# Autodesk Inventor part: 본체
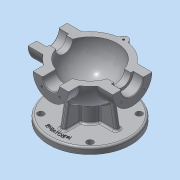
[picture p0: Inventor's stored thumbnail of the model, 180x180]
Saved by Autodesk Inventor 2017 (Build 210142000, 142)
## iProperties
Created: 2015-12
Part Number: 본체
Material: 알루미늄 6061
Document SubType Name: Modeling
Designer: mduedu
Density: 2.71 g/cm^3
Mass: 966.367 g
Surface Area: 788.536 cm^2
Volume: 356.593 cm^3
Appearance: 알루미늄 - 평지
Author: mduedu
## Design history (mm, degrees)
sketch "스케치1"
  geometry: L1 (-53, 0)-(53, 0); A1 r 53 centre (0, 0) between (53, 0) and (-53, 0); 2 further points
  constraints: 2 coincident, 2 end point, 2 point on circle, 1 centre point, 1 horizontal, 1 midpoint
  dimensions: "d0" = 53 radius of A1
revolve "회전1" sketch "스케치1" stored, may be unused: angle "d2" = 90 deg
feature "쉘1" dims "d11" = 10
node "작업 평면1"
sketch "스케치2"
  geometry: C1 r 31 at (0, 0); 1 further point
  constraints: 1 centre point, 1 coincident
  dimensions: "d4" = 62 diameter of C1
extrude "돌출1" join sketch "스케치2" stored distance "d5" = 10; taper "d6" = 0 deg
node "작업 평면2"
sketch "스케치3"
  geometry: C1 r 28 at (0, 0); 1 further point
  constraints: 1 centre point, 1 coincident
  dimensions: "d8" = 56 diameter of C1
extrude "돌출2" join sketch "스케치3" stored distance "d9" = 10; taper "d10" = 0 deg
hole "구멍1" diameter "d14" = 35; stored, may be unused: countersink angle "d18" = 90 deg, drill point angle "d20" = 0 deg; dims "d12" = 10, "d13" = 10, "d15" = 6, "d16" = 4, "d17" = 2, "d19" = 16
hole "구멍2" diameter "d23" = 27; stored, may be unused: countersink angle "d27" = 90 deg, drill point angle "d29" = 0 deg; dims "d21" = 10, "d22" = 10, "d24" = 6, "d25" = 4, "d26" = 2, "d28" = 16
fillet "모깎기1" dims "d30" = 0.3
hole "구멍3" diameter "d33" = 26; stored, may be unused: countersink angle "d37" = 90 deg, drill point angle "d39" = 0 deg; dims "d31" = 10, "d32" = 10, "d34" = 6, "d35" = 4, "d36" = 2, "d38" = 16
chamfer "모따기1" distance "d40" = 1; stored, may be unused: second distance "d41" = 2, angle "d42" = 45 deg
sketch "스케치4"
  geometry: L1 (0, 0)-(0, -25); L2 (0, 0)-(-17.678, -17.678); A1 r 25 centre (0, 0) between (-17.678, -17.678) and (0, -25); 1 further point
  constraints: 4 end point, 2 point on circle, 1 centre point, 1 coincident, 1 vertical
  dimensions: "d43" = 50 diameter of A1; "d47" = 45 deg angle of L1 L2
hole "구멍4" sketch "스케치4" at (-17.678, -17.678) diameter "d49" = 3.242; stored, may be unused: countersink angle "d53" = 90 deg, drill point angle "d55" = 118 deg; dims "d50" = 11, "d51" = 4, "d52" = 2, "d54" = 13
sketch "스케치5"
  geometry: L1 (0, 0)-(0, -20); L2 (0, 0)-(-14.142, -14.142); A1 r 20 centre (0, 0) between (0, -20) and (-14.142, -14.142); 2 further points
  constraints: 4 end point, 2 coincident, 2 point on circle, 1 centre point, 1 vertical
  dimensions: "d59" = 40 diameter of A1; "d65" = 45 deg angle of L1 L2
hole "구멍5" sketch "스케치5" at (-14.142, -14.142) diameter "d67" = 3.242; stored, may be unused: countersink angle "d71" = 90 deg, drill point angle "d73" = 118 deg; dims "d68" = 8, "d69" = 4, "d70" = 2, "d72" = 10
node "작업 평면3"
sketch "스케치6"
  geometry: C1 r 65 at (0, 0); 1 further point
  constraints: 1 centre point, 1 coincident
  dimensions: "d78" = 130 diameter of C1
extrude "돌출3" join sketch "스케치6" distance "d80" = 10; taper "d81" = 0 deg
sketch "스케치7"
  geometry: C1 r 20 at (0, 0); 1 further point
  constraints: 1 centre point, 1 coincident
  dimensions: "d82" = 40 diameter of C1
extrude "돌출4" join sketch "스케치7" stored distance "d84" = 10; taper "d85" = 0 deg
sketch "스케치8"
  geometry: 2 further points
  constraints: 1 coincident
hole "구멍6" sketch "스케치8" at (0, 0) diameter "d86" = 20; stored, may be unused: countersink angle "d90" = 90 deg, drill point angle "d92" = 118 deg; dims "d87" = 7, "d88" = 40, "d89" = 5, "d91" = 10
fillet "모깎기2" dims "d93" = 0.3
sketch "스케치9"
  geometry: L1 (65, -75)-(-65, -75) reference; L2 (-45, -75)-(-38.245, -36.692); A1 r 53 centre (0, 0) between (42.988, 31) and (42.988, -31) reference; 1 further point
  constraints: 2 end point, 1 point on circle, 1 point on line
  dimensions: "d94" = 45 horizontal distance of L2.start point (0, 0); "d95" = 80 deg angle of L2 L1
feature "리브1" sketch "스케치9" dims "d96" = 1, "d97" = 8, "d98" = 0, "d99" = 0, "d100" = 1, "d101" = 1
sketch "스케치10"
  geometry: L1 (0, 0)-(0, -55); L2 (0, 0)-(-38.891, -38.891); A1 r 55 centre (0, 0) between (0, -55) and (-38.891, -38.891); 2 further points
  constraints: 4 end point, 2 coincident, 2 point on circle, 1 centre point, 1 vertical
  dimensions: "d105" = 110 diameter of A1; "d107" = 45 deg angle of L1 L2
hole "구멍7" sketch "스케치10" at (-38.891, -38.891) diameter "d109" = 10; stored, may be unused: countersink angle "d113" = 90 deg, drill point angle "d115" = 118 deg; dims "d110" = 7, "d111" = 40, "d112" = 5, "d114" = 10
fillet "모깎기3" dims "d120" = 3
fillet "모깎기4" dims "d121" = 3, "d122" = 3
fillet "모깎기5" dims "d123" = 3
fillet "모깎기6" dims "d124" = 3
sketch "스케치11"
  geometry: C1 r 5 at (-38.891, 38.891) reference; C2 r 5 at (38.891, 38.891) reference; C3 r 5 at (38.891, -38.891) reference; C4 r 5 at (-38.891, -38.891) reference; C5 r 20 at (0, 0) reference; C6 r 65 at (0, 0) reference; 1 further point
  constraints: 3 other
feature "엠보싱1" sketch "스케치11" dims "d125" = 0.5, "d126" = 0
sketch "스케치12"
  geometry: L1 (0, 100)-(0, -100); L2 (0, 100)-(100, 100); L3 (100, 100)-(100, -100); L4 (100, -100)-(0, -100); 2 further points
  constraints: 8 end point, 3 perpendicular, 1 coincident, 1 midpoint, 1 vertical
  dimensions: "d127" = 200 distance of L2.end L3.end; "d129" = 100 distance between parallel lines of L1 L3
extrude "돌출5" cut sketch "스케치12" stored distance "d130" = 10; taper "d131" = 0 deg
sketch "스케치13"
  geometry: C1 r 7 at (0, 53); A1 r 53 centre (0, 0) between (42.113, 32.179) and (-42.113, 32.179) reference; 1 further point
  constraints: 1 centre point, 1 point on circle
  dimensions: "d132" = 14 diameter of C1
extrude "돌출6" join sketch "스케치13" distance "d134" = 15; taper "d135" = 0 deg
hole "구멍8" diameter "d139" = 3.242; stored, may be unused: countersink angle "d143" = 90 deg, drill point angle "d145" = 118 deg; dims "d140" = 8, "d141" = 4, "d142" = 2, "d144" = 10, "d148" = 10, "d149" = 10
fillet "모깎기7" dims "d146" = 3
fillet "모깎기8" dims "d147" = 3
node "솔리드1"
mirror "대칭1"
mirror "대칭2"
pattern_circular "원형 패턴1" dims angle "d57" = 360 deg
mirror "대칭3"
pattern_circular "원형 패턴2" dims angle "d75" = 360 deg
pattern_circular "원형 패턴3" dims angle "d103" = 360 deg
pattern_circular "원형 패턴4" dims angle "d118" = 360 deg
node "투영된 루프1"
other parameters: "d3" = 67, "d7" = 62, "d77" = -85
